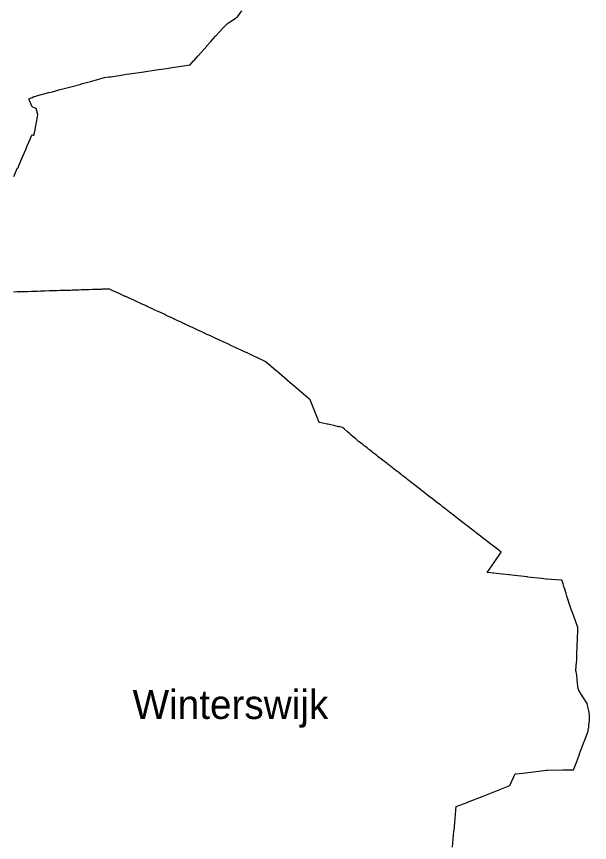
# Model space of a CAD drawing. Extents: x 113371 to 291721, y 393993 to 520143.
# Drawn here: x 244405 to 254304, y 441487 to 455750 of the extents above; entities that cross this region are included whole.
import ezdxf

# ---------------------------------------------------------------- set-up
doc = ezdxf.new("R2010")
doc.units = 0
doc.layers.add('Default', color=7, linetype='Continuous')
doc.layers.add('plaatsnamen', color=7, linetype='Continuous')

msp = doc.modelspace()

# ---------------------------------------------------------------- linework, layer by layer
at = {"layer": 'Default'}
for points in [[(245519.885625, 454585.1625), (245707.435625, 454635.5125), (245708.585625, 454635.8125), (245803.905625, 454662.0025), (245927.265625, 454695.6525), (246000.985625, 454707.5125), (246032.795625, 454711.7625), (246103.035625, 454721.8025), (246210.135625, 454737.9725), (246307.365625, 454752.2825), (246307.645625, 454752.3325), (246357.745625, 454759.7025), (246604.405625, 454796.0025), (246816.225625, 454826.9425), (246909.005625, 454840.8825), (246996.785625, 454853.8625), (247093.145625, 454868.0125), (247404.635625, 454915.6725), (247459.545625, 454976.9325), (247469.235625, 454987.9125), (247543.505625, 455072.0025), (247694.055625, 455241.1225), (247694.285625, 455241.3825), (247764.765625, 455320.1025), (247843.395625, 455408.7025), (247918.825625, 455493.2025), (247979.395625, 455561.0525), (248047.135625, 455627.1125), (248069.775625, 455642.3625), (248097.555625, 455660.5325), (248098.565625, 455661.1925), (248189.915625, 455721.0825), (248221.715625, 455742.2925), (248296.085625, 455847.9225)], [(244620.855625, 453591.7525), (244668.335625, 453704.3125), (244672.935625, 453706.6525), (244693.145625, 453702.1325), (244695.705625, 453701.8125), (244698.475625, 453701.9525), (244701.475625, 453702.4525), (244703.695625, 453703.3925), (244706.635625, 453705.2725), (244708.855625, 453707.6525), (244710.135625, 453709.6725), (244711.085625, 453712.4825), (244711.945625, 453716.6025), (244725.035625, 453791.1325), (244728.355625, 453807.2425), (244754.135625, 453953.4225), (244773.055625, 454056.2025), (244743.565625, 454161.4225), (244685.165625, 454185.3925), (244679.255625, 454189.0325), (244676.095625, 454191.5725), (244674.065625, 454194.2825), (244668.995625, 454202.6525), (244616.955625, 454326.7825), (244674.695625, 454352.7025), (244678.755625, 454354.4825), (244706.095625, 454366.4325), (244738.435625, 454375.0525), (244745.805625, 454377.0425), (244752.245625, 454378.7825), (244965.795625, 454436.4525), (245025.175625, 454452.5825), (245025.275625, 454452.6025), (245085.315625, 454468.9125), (245136.635625, 454482.9325), (245345.085625, 454538.8225), (245519.365625, 454585.0225), (245519.885625, 454585.1625)], [(244359.175625, 452989.0625), (244421.395625, 453137.5625), (244435.365625, 453138.2625), (244436.885625, 453150.5025), (244440.895625, 453163.3225), (244481.745625, 453259.5825), (244498.755625, 453301.3525), (244563.645625, 453456.1225), (244589.075625, 453515.7525), (244620.855625, 453591.7525)], [(246227.175625, 450944.4125), (246212.905625, 450950.9625), (246176.925625, 450967.4725), (246138.865625, 450984.7525), (246100.025625, 451003.1625), (246059.145625, 451021.9425), (246023.335625, 451038.2925), (246012.335625, 451043.0425), (245965.365625, 451042.1025), (245905.075625, 451040.2525), (245883.675625, 451039.6125), (245883.445625, 451039.6025), (245865.605625, 451039.0725), (245830.335625, 451038.0425), (245774.165625, 451036.2525), (245716.605625, 451034.1625), (245661.035625, 451032.6925), (245615.605625, 451031.2525), (245571.895625, 451029.9125), (245523.585625, 451028.1025), (245481.055625, 451026.9425), (245445.505625, 451026.1925), (245418.005625, 451025.1025), (245376.635625, 451024.0725), (245367.175625, 451022.9425), (245334.675625, 451021.9725), (245320.025625, 451021.7225), (245254.895625, 451019.3525), (245160.505625, 451016.4425), (245108.135625, 451014.4425), (245045.025625, 451012.7925), (244970.975625, 451010.6625), (244896.145625, 451008.1025), (244816.825625, 451005.5725), (244765.635625, 451003.9125), (244725.675625, 451002.8225), (244664.085625, 451001.0025), (244599.445625, 450998.9125)], [(244599.445625, 450998.9125), (244537.145625, 450997.2225), (244474.465625, 450995.3825), (244418.165625, 450993.6625), (244352.475625, 450991.4125)], [(247278.055625, 450456.2925), (247236.885625, 450476.0725), (247202.945625, 450491.5725), (247167.785625, 450508.1925), (247141.355625, 450520.5825), (247123.635625, 450528.8825), (247075.675625, 450551.3825), (247031.615625, 450571.8825), (246993.185625, 450589.6425), (246992.545625, 450589.9425), (246988.825625, 450591.6625), (246987.605625, 450592.2525), (246986.005625, 450593.0325), (246983.885625, 450594.0625), (246967.055625, 450602.2525), (246930.035625, 450619.4725), (246893.245625, 450636.5425), (246850.465625, 450656.4725), (246797.355625, 450681.6925), (246754.305625, 450701.5725), (246709.385625, 450722.5425), (246668.995625, 450741.3525), (246663.015625, 450744.1325), (246660.195625, 450745.4525), (246658.425625, 450746.2725), (246647.855625, 450751.1925), (246642.605625, 450753.9125), (246619.465625, 450764.9725), (246585.995625, 450780.1925), (246550.555625, 450796.6325), (246502.575625, 450818.6925), (246441.135625, 450846.6925), (246379.915625, 450874.8225), (246318.695625, 450902.9125), (246294.715625, 450912.9125), (246284.335625, 450917.5125), (246283.855625, 450917.7225), (246227.175625, 450944.4125)], [(249041.395625, 449504.4125), (248946.765625, 449585.0125), (248940.085625, 449590.7025), (248901.605625, 449623.4725), (248889.755625, 449633.3525), (248803.575625, 449707.7325), (248796.585625, 449713.7525), (248701.465625, 449795.4425), (248558.715625, 449861.3525), (248545.565625, 449867.4925), (248493.855625, 449891.6625), (248387.005625, 449940.9125), (248344.865625, 449960.7225), (248286.215625, 449988.4125), (248258.285625, 450001.7225), (248207.645625, 450025.2525), (248161.185625, 450046.9325), (248146.665625, 450053.7125), (248120.385625, 450066.0025), (248045.055625, 450101.1925), (248014.695625, 450115.1725), (247973.195625, 450134.2925), (247897.835625, 450169.2225), (247834.605625, 450198.2525), (247757.495625, 450233.6925), (247740.245625, 450241.5825), (247672.725625, 450272.4725), (247654.345625, 450281.0425), (247605.255625, 450303.9125), (247536.415625, 450336.1025), (247458.965625, 450372.1025), (247389.325625, 450404.7925), (247339.005625, 450428.1325), (247312.385625, 450440.3825), (247298.325625, 450446.6925), (247290.505625, 450450.4425), (247289.115625, 450451.0925), (247278.055625, 450456.2925)], [(250267.305625, 448454.8625), (250222.705625, 448493.1625), (250183.735625, 448526.7425), (250162.725625, 448544.8425), (250119.735625, 448581.9225), (250066.555625, 448627.6925), (250039.805625, 448650.6725), (250039.365625, 448651.0525), (249991.145625, 448662.4625), (249973.045625, 448666.5725), (249964.935625, 448668.4025), (249964.775625, 448668.4425), (249946.435625, 448672.6025), (249899.725625, 448683.2825), (249888.505625, 448685.8425), (249834.775625, 448698.0925), (249814.415625, 448702.7625), (249813.595625, 448702.9425), (249808.145625, 448704.1925), (249805.975625, 448704.6125), (249781.655625, 448709.2625), (249781.515625, 448709.2025), (249775.875625, 448710.5025), (249775.305625, 448710.6425), (249774.635625, 448710.7925), (249773.045625, 448711.1625), (249719.275625, 448723.6325), (249665.535625, 448736.2925), (249636.495625, 448742.1925), (249618.475625, 448786.2225), (249571.645625, 448900.5425), (249524.475625, 449016.3225), (249476.755625, 449131.8525), (249400.255625, 449198.1025), (249320.925625, 449266.0725), (249228.445625, 449345.3225), (249132.975625, 449426.9125), (249041.395625, 449504.4125)], [(250913.175625, 447948.2225), (250911.245625, 447949.7425), (250902.975625, 447956.2225), (250873.135625, 447979.6325), (250865.665625, 447985.5425), (250853.505625, 447995.1525), (250850.855625, 447997.2525), (250821.785625, 448020.1025), (250809.975625, 448029.2025), (250788.885625, 448045.4425), (250763.255625, 448065.6025), (250730.605625, 448090.9125), (250727.145625, 448093.5225), (250702.005625, 448112.5425), (250677.195625, 448131.7225), (250655.285625, 448148.6925), (250628.645625, 448169.9425), (250628.225625, 448170.2725), (250606.505625, 448187.1325), (250584.745625, 448204.0425), (250567.725625, 448216.9725), (250562.125625, 448221.3825), (250547.825625, 448232.6325), (250527.395625, 448248.3525), (250494.105625, 448274.1925), (250462.225625, 448299.3825), (250437.895625, 448318.3525), (250427.245625, 448326.3725), (250413.005625, 448336.6825), (250400.455625, 448346.5925), (250386.555625, 448357.1525), (250369.825625, 448370.4325), (250346.205625, 448388.8725), (250325.455625, 448404.6825), (250315.215625, 448414.0825), (250303.185625, 448424.3925), (250292.995625, 448433.1325), (250267.305625, 448454.8625)], [(252479.525625, 446732.2025), (252182.625625, 446962.1625), (252167.595625, 446973.8225), (252122.605625, 447008.7125), (251933.395625, 447155.4325), (251883.985625, 447193.7425), (251800.765625, 447258.3225), (251766.485625, 447284.9125), (251734.685625, 447309.5925), (251661.615625, 447366.2925), (251585.765625, 447425.1425), (251542.745625, 447458.2425), (251506.115625, 447486.4125), (251391.315625, 447575.8725), (251288.275625, 447656.1525), (251211.895625, 447714.7525), (251204.755625, 447720.2225), (251204.855625, 447720.3825), (251189.785625, 447732.4125), (251188.925625, 447733.1025), (251162.805625, 447753.2225), (251157.305625, 447757.5425), (251134.335625, 447775.5425), (251108.565625, 447795.5525), (251103.915625, 447799.1625), (251077.165625, 447819.8525), (251061.435625, 447832.2825), (251048.175625, 447842.7525), (251015.055625, 447868.6325), (250984.475625, 447892.1025), (250972.975625, 447901.1525), (250972.285625, 447901.6925), (250960.245625, 447911.1625), (250928.665625, 447936.0725), (250921.055625, 447942.0425), (250920.305625, 447942.6325), (250919.825625, 447943.0025), (250913.175625, 447948.2225)], [(253974.695625, 445550.3525), (253968.935625, 445565.8225), (253956.855625, 445598.2725), (253951.725625, 445615.1925), (253939.505625, 445655.4225), (253914.225625, 445738.6425), (253906.925625, 445762.6825), (253900.025625, 445785.3825), (253898.635625, 445789.9625), (253888.955625, 445821.8425), (253877.535625, 445859.4225), (253862.235625, 445909.8125), (253849.745625, 445950.9125), (253830.845625, 446013.1125), (253826.595625, 446013.4725), (253818.615625, 446014.1525), (253564.025625, 446035.6225), (253558.035625, 446036.1325), (253550.085625, 446036.7925), (253480.015625, 446044.6325), (253476.595625, 446045.0125), (253239.685625, 446071.2925), (253226.845625, 446072.7225), (252965.385625, 446101.8325), (252963.825625, 446102.0025), (252919.605625, 446106.9125), (252909.055625, 446108.0825), (252799.215625, 446120.2725), (252745.005625, 446125.9625), (252648.475625, 446136.0825), (252536.075625, 446147.8825), (252656.555625, 446323.0225), (252777.265625, 446500.8125), (252717.895625, 446546.9525), (252683.845625, 446573.4225), (252582.075625, 446652.5125), (252492.645625, 446722.0225), (252479.525625, 446732.2025)], [(254301.675625, 443662.9625), (254298.555625, 443731.1125), (254297.865625, 443734.2925), (254296.325625, 443741.4325), (254293.665625, 443753.6825), (254292.415625, 443759.4425), (254271.855625, 443854.3525), (254270.005625, 443862.8525), (254264.765625, 443887.0425), (254189.555625, 444002.9225), (254170.995625, 444031.5125), (254167.005625, 444037.6725), (254124.235625, 444103.5725), (254121.685625, 444107.4925), (254119.355625, 444111.0925), (254117.735625, 444113.5825), (254111.555625, 444143.6025), (254102.755625, 444186.3625), (254091.185625, 444295.8225), (254090.715625, 444300.2025), (254090.115625, 444305.8825), (254083.695625, 444366.7825), (254083.215625, 444371.3425), (254071.755625, 444439.7025), (254069.585625, 444444.4025), (254067.465625, 444448.9725), (254077.015625, 444537.0625), (254083.215625, 444632.7925), (254086.985625, 444744.3825), (254087.185625, 444749.4625), (254091.715625, 444862.6525), (254097.375625, 445034.5225), (254100.305625, 445123.7125), (254100.425625, 445127.4525), (254104.195625, 445202.2425), (254031.835625, 445396.7425), (253975.715625, 445547.5925), (253974.695625, 445550.3525)], [(251938.335625, 441408.5925), (251962.915625, 441680.2725), (251963.885625, 441691.0525), (252001.445625, 442106.3325), (252189.695625, 442180.2225), (252191.975625, 442181.1125), (252194.375625, 442182.0525), (252467.025625, 442288.0025), (252928.575625, 442468.2225), (252929.155625, 442469.5325), (253019.215625, 442670.2925), (253151.615625, 442686.2525), (253560.895625, 442735.5725), (253563.145625, 442735.8425), (253580.625625, 442736.1125), (253842.845625, 442740.0225), (253986.385625, 442742.1625), (254025.745625, 442742.7425), (254027.755625, 442742.7725), (254082.785625, 442887.4425), (254100.475625, 442933.9525), (254129.435625, 443010.1125), (254132.145625, 443017.1625), (254168.045625, 443110.6625), (254215.245625, 443233.5625), (254218.945625, 443243.2125), (254282.485625, 443408.7425), (254284.305625, 443421.1025), (254290.085625, 443460.3625), (254290.625625, 443465.8125), (254295.075625, 443511.1225), (254302.875625, 443590.5725), (254304.325625, 443605.3025), (254304.215625, 443607.6125), (254304.175625, 443608.5625), (254302.265625, 443650.1125), (254301.895625, 443658.3325), (254301.675625, 443662.9625)]]:
    msp.add_lwpolyline(points, dxfattribs=at)

# ---------------------------------------------------------------- texts
at = {"layer": 'plaatsnamen'}
msp.add_text('Winterswijk', height=500, dxfattribs=at).set_placement((246410.472638, 443619.998607))

doc.saveas('drawing.dxf')
